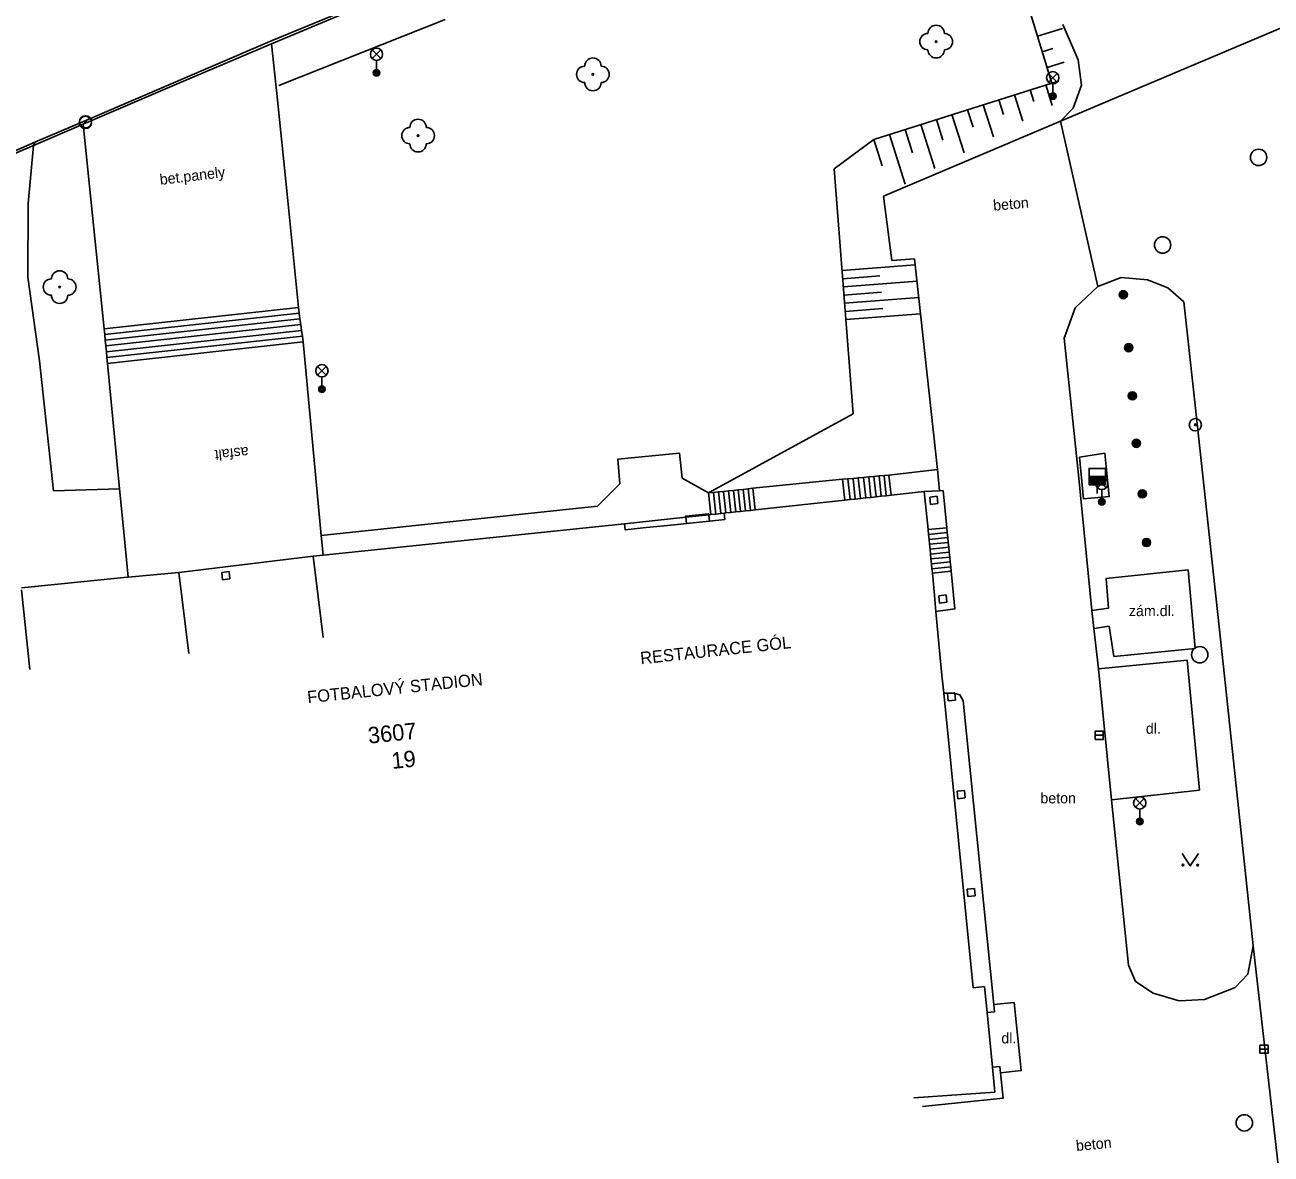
# Model space of a CAD drawing. Extents: x -539694 to -539148, y -1156467 to -1155920.
# Drawn here: x -539556.6 to -539480.5, y -1156122.8 to -1156053.8 of the extents above; entities that cross this region are included whole.
import ezdxf

# ---------------------------------------------------------------- set-up
doc = ezdxf.new("R2010")
doc.units = 0
for name, color, linetype in [('Vrstva 10', 7, 'Continuous'), ('Vrstva 11', 7, 'Continuous'), ('Vrstva 14', 7, 'Continuous'), ('Vrstva 15', 7, 'Continuous'), ('Vrstva 21', 7, 'Continuous'), ('Vrstva 22', 7, 'Continuous'), ('Vrstva 23', 7, 'Continuous'), ('Vrstva 25', 7, 'Continuous'), ('Vrstva 27', 7, 'Continuous'), ('Vrstva 28', 7, 'Continuous'), ('Vrstva 33', 7, 'Continuous'), ('Vrstva 36', 7, 'Continuous'), ('Vrstva 40', 7, 'Continuous'), ('Vrstva 41', 7, 'Continuous'), ('Vrstva 46', 7, 'Continuous'), ('Vrstva 47', 7, 'Continuous'), ('Vrstva 5', 7, 'Continuous'), ('Vrstva 6', 7, 'Continuous')]:
    doc.layers.add(name, color=color, linetype=linetype)

msp = doc.modelspace()

# ---------------------------------------------------------------- linework, layer by layer
at = {"layer": 'Vrstva 10'}
msp.add_lwpolyline([(-539514.829, -1156084.157), (-539514.87, -1156083.768), (-539514.877, -1156083.703), (-539516.27, -1156083.85), (-539516.263, -1156083.915), (-539516.222, -1156084.304)], dxfattribs=at)
at = {"layer": 'Vrstva 11'}
for p, q in [((-539493.4, -1156059.73), (-539469, -1156049.41)), ((-539541.52, -1156054.81), (-539532.19, -1156050.92)), ((-539541.55, -1156055), (-539532.14, -1156051.05)), ((-539553.04, -1156059.75), (-539541.52, -1156054.81)), ((-539547.07, -1156057.35), (-539541.55, -1156055)), ((-539541.55, -1156055), (-539541.23, -1156058.03)), ((-539553.06, -1156059.92), (-539547.07, -1156057.35)), ((-539541.23, -1156058.03), (-539540.61, -1156064.18)), ((-539556.09, -1156061.22), (-539553.06, -1156059.92)), ((-539556, -1156061.02), (-539553.04, -1156059.75)), ((-539552.48, -1156065.49), (-539553.06, -1156059.92)), ((-539493.4, -1156059.73), (-539504.2, -1156064.3)), ((-539493.4, -1156059.73), (-539491.13, -1156069.82)), ((-539556, -1156061.02), (-539562.35, -1156063.74)), ((-539562.25, -1156063.84), (-539556.09, -1156061.22)), ((-539556.09, -1156061.22), (-539556, -1156061.02)), ((-539540.61, -1156064.18), (-539539.916, -1156071.114)), ((-539551.767, -1156072.403), (-539552.48, -1156065.49)), ((-539502.31, -1156068.14), (-539500.9, -1156081)), ((-539555.72, -1156074.36), (-539556.44, -1156069.26)), ((-539485.14, -1156077.43), (-539485.88, -1156070.76)), ((-539551.767, -1156072.403), (-539539.916, -1156071.114)), ((-539551.735, -1156072.751), (-539539.868, -1156071.46)), ((-539551.703, -1156073.099), (-539539.819, -1156071.807)), ((-539551.671, -1156073.448), (-539539.771, -1156072.154)), ((-539551.639, -1156073.806), (-539539.721, -1156072.509)), ((-539551.606, -1156074.164), (-539539.672, -1156072.866)), ((-539493.17, -1156072.98), (-539492.31, -1156081.32)), ((-539539.625, -1156073.2), (-539551.573, -1156074.524)), ((-539538.523, -1156085.033), (-539539.625, -1156073.2)), ((-539554.86, -1156082.31), (-539555.72, -1156074.36)), ((-539483.4, -1156093.63), (-539485.14, -1156077.43)), ((-539505.106, -1156081.454), (-539504.972, -1156082.702)), ((-539504.788, -1156081.424), (-539504.654, -1156082.668)), ((-539504.478, -1156081.396), (-539504.345, -1156082.634)), ((-539504.17, -1156081.368), (-539504.037, -1156082.601)), ((-539503.87, -1156081.34), (-539503.737, -1156082.57)), ((-539500.9, -1156081), (-539500.79, -1156082.3)), ((-539492.31, -1156081.32), (-539491.48, -1156089.61)), ((-539550.828, -1156082.186), (-539554.86, -1156082.31)), ((-539516.5, -1156081.52), (-539514.88, -1156082.43)), ((-539512.766, -1156082.214), (-539512.624, -1156083.527)), ((-539512.468, -1156082.182), (-539512.326, -1156083.495)), ((-539512.17, -1156082.15), (-539506.7, -1156081.6)), ((-539512.17, -1156082.15), (-539512.028, -1156083.463)), ((-539506.7, -1156081.6), (-539506.563, -1156082.874)), ((-539506.38, -1156081.571), (-539506.244, -1156082.839)), ((-539506.062, -1156081.541), (-539505.926, -1156082.805)), ((-539505.743, -1156081.512), (-539505.608, -1156082.771)), ((-539505.425, -1156081.483), (-539505.29, -1156082.737)), ((-539514.88, -1156082.43), (-539514.74, -1156083.754)), ((-539514.576, -1156082.399), (-539514.433, -1156083.722)), ((-539514.268, -1156082.367), (-539514.125, -1156083.689)), ((-539513.96, -1156082.335), (-539513.817, -1156083.656)), ((-539513.662, -1156082.304), (-539513.519, -1156083.624)), ((-539513.364, -1156082.273), (-539513.221, -1156083.592)), ((-539513.064, -1156082.242), (-539512.922, -1156083.56)), ((-539501.72, -1156082.352), (-539500.79, -1156082.3)), ((-539538.523, -1156085.033), (-539521.66, -1156083.23)), ((-539550.614, -1156084.39), (-539550.303, -1156087.57)), ((-539538.412, -1156086.227), (-539538.523, -1156085.033)), ((-539500.341, -1156084.555), (-539501.486, -1156084.67)), ((-539500.311, -1156084.852), (-539501.455, -1156084.968)), ((-539500.281, -1156085.151), (-539501.425, -1156085.266)), ((-539500.251, -1156085.45), (-539501.395, -1156085.565)), ((-539500.22, -1156085.748), (-539501.365, -1156085.863)), ((-539500.19, -1156086.047), (-539501.335, -1156086.162)), ((-539500.16, -1156086.344), (-539501.305, -1156086.46)), ((-539500.13, -1156086.644), (-539501.275, -1156086.759)), ((-539500.1, -1156086.942), (-539501.245, -1156087.057)), ((-539500.072, -1156087.215), (-539501.218, -1156087.33)), ((-539490.61, -1156087.65), (-539485.6, -1156087.13)), ((-539491.48, -1156089.61), (-539491.36, -1156090.71)), ((-539491.36, -1156090.71), (-539491.08, -1156093.17)), ((-539491.08, -1156093.17), (-539485.66, -1156092.65)), ((-539485.66, -1156092.65), (-539484.91, -1156100.58)), ((-539491.08, -1156093.17), (-539490.28, -1156101.18)), ((-539481.64, -1156110.08), (-539483.4, -1156093.63)), ((-539499.34, -1156095.12), (-539497.47, -1156113.68)), ((-539484.91, -1156100.58), (-539490.28, -1156101.18)), ((-539490.28, -1156101.18), (-539489.24, -1156111.26)), ((-539481.97, -1156111.82), (-539481.64, -1156110.08)), ((-539481.64, -1156110.08), (-539479.7, -1156127.1))]:
    msp.add_line(p, q, dxfattribs=at)
for points in [[(-539493.4, -1156059.73), (-539492.62, -1156058.93), (-539492.11, -1156057.52), (-539492.33, -1156055.98), (-539493.25, -1156053.83)], [(-539556.44, -1156069.26), (-539556.41, -1156064.75), (-539556.09, -1156061.22)], [(-539504.2, -1156064.3), (-539503.69, -1156068.23), (-539502.31, -1156068.14)], [(-539485.88, -1156070.76), (-539486.85, -1156069.91), (-539488.09, -1156069.41), (-539489.69, -1156069.27), (-539491.13, -1156069.82)], [(-539491.13, -1156069.82), (-539492.51, -1156071.12), (-539493.17, -1156072.98)], [(-539539.916, -1156071.114), (-539539.868, -1156071.46), (-539539.819, -1156071.807), (-539539.771, -1156072.154), (-539539.721, -1156072.509), (-539539.672, -1156072.866), (-539539.625, -1156073.2)], [(-539551.573, -1156074.524), (-539551.606, -1156074.164), (-539551.639, -1156073.806), (-539551.671, -1156073.448), (-539551.703, -1156073.099), (-539551.735, -1156072.751), (-539551.767, -1156072.403)], [(-539551.573, -1156074.524), (-539550.828, -1156082.186), (-539550.614, -1156084.39)], [(-539521.66, -1156083.23), (-539520.29, -1156081.87), (-539520.42, -1156080.37), (-539516.66, -1156080), (-539516.5, -1156081.52)], [(-539492.25, -1156080.24), (-539490.7, -1156080), (-539490.42, -1156082.65), (-539491.99, -1156082.8), (-539492.25, -1156080.24)], [(-539506.7, -1156081.6), (-539506.38, -1156081.571), (-539506.062, -1156081.541), (-539505.743, -1156081.512), (-539505.425, -1156081.483), (-539505.106, -1156081.454), (-539504.788, -1156081.424), (-539504.478, -1156081.396), (-539504.17, -1156081.368), (-539503.87, -1156081.34), (-539500.9, -1156081)], [(-539514.88, -1156082.43), (-539514.576, -1156082.399), (-539514.268, -1156082.367), (-539513.96, -1156082.335), (-539513.662, -1156082.304), (-539513.364, -1156082.273), (-539513.064, -1156082.242), (-539512.766, -1156082.214), (-539512.468, -1156082.182), (-539512.17, -1156082.15)], [(-539500.79, -1156082.3), (-539500.57, -1156082.29), (-539500.341, -1156084.555), (-539500.311, -1156084.852), (-539500.281, -1156085.151), (-539500.251, -1156085.45), (-539500.22, -1156085.748), (-539500.19, -1156086.047), (-539500.16, -1156086.344), (-539500.13, -1156086.644), (-539500.1, -1156086.942), (-539500.072, -1156087.215), (-539499.84, -1156089.51), (-539501.007, -1156089.677)], [(-539485.6, -1156087.13), (-539485.18, -1156091.93), (-539490.15, -1156092.42)], [(-539491.48, -1156089.61), (-539490.46, -1156089.46), (-539490.61, -1156087.65)], [(-539490.15, -1156092.42), (-539490.43, -1156090.57), (-539491.36, -1156090.71)], [(-539500.53, -1156094.66), (-539500.118, -1156094.66), (-539499.93, -1156094.66), (-539499.85, -1156094.68), (-539499.54, -1156094.76), (-539499.34, -1156095.12)], [(-539489.24, -1156111.26), (-539488.82, -1156112.26), (-539487.75, -1156112.97), (-539486.15, -1156113.44), (-539484.61, -1156113.36), (-539482.74, -1156112.63), (-539481.97, -1156111.82)], [(-539497.47, -1156113.68), (-539497.43, -1156114.12), (-539497.88, -1156114.16)], [(-539497.47, -1156113.68), (-539496.23, -1156113.55), (-539495.8, -1156117.71), (-539497.06, -1156117.84)], [(-539497.06, -1156117.84), (-539496.9, -1156119.4), (-539501.826, -1156119.896)], [(-539497.06, -1156117.84), (-539497.1, -1156117.46), (-539497.55, -1156117.5)]]:
    msp.add_lwpolyline(points, dxfattribs=at)
at = {"layer": 'Vrstva 14'}
for p, q in [((-539493.93, -1156057.4), (-539495.35, -1156052.75)), ((-539504.79, -1156060.84), (-539493.93, -1156057.4)), ((-539504.79, -1156060.84), (-539507.219, -1156062.649)), ((-539506.049, -1156077.595), (-539507.219, -1156062.649)), ((-539514.88, -1156082.43), (-539506.049, -1156077.595))]:
    msp.add_line(p, q, dxfattribs=at)
at = {"layer": 'Vrstva 15'}
for p, q in [((-539494.806, -1156054.531), (-539493.276, -1156054.064)), ((-539494.514, -1156055.487), (-539493.871, -1156055.291)), ((-539494.222, -1156056.444), (-539493.178, -1156056.125)), ((-539495.257, -1156057.82), (-539495.031, -1156058.533)), ((-539494.304, -1156057.518), (-539493.909, -1156058.763)), ((-539493.93, -1156057.4), (-539493.529, -1156057.278)), ((-539497.163, -1156058.424), (-539496.881, -1156059.317)), ((-539496.21, -1156058.122), (-539495.702, -1156059.727)), ((-539500.023, -1156059.33), (-539499.287, -1156061.656)), ((-539499.07, -1156059.028), (-539498.73, -1156060.101)), ((-539498.117, -1156058.726), (-539497.494, -1156060.692)), ((-539501.93, -1156059.934), (-539501.079, -1156062.621)), ((-539500.977, -1156059.632), (-539500.58, -1156060.885)), ((-539504.79, -1156060.84), (-539504.279, -1156062.454)), ((-539503.837, -1156060.538), (-539502.871, -1156063.585)), ((-539502.883, -1156060.236), (-539502.429, -1156061.669)), ((-539502.266, -1156068.502), (-539506.733, -1156068.851)), ((-539504.43, -1156069.172), (-539506.693, -1156069.349)), ((-539502.157, -1156069.495), (-539506.654, -1156069.847)), ((-539504.334, -1156070.167), (-539506.615, -1156070.346)), ((-539502.049, -1156070.49), (-539506.576, -1156070.844)), ((-539504.238, -1156071.163), (-539506.537, -1156071.343)), ((-539501.94, -1156071.484), (-539506.498, -1156071.841))]:
    msp.add_line(p, q, dxfattribs=at)
at = {"layer": 'Vrstva 21'}
for centre, radius in [((-539552.91, -1156059.77), 0.375), ((-539552.92, -1156059.8), 0.375), ((-539552.92, -1156059.8), 0.05), ((-539552.91, -1156059.77), 0.05), ((-539485.17, -1156078.27), 0.375), ((-539485.17, -1156078.27), 0.05)]:
    msp.add_circle(centre, radius, dxfattribs=at)
at = {"layer": 'Vrstva 22'}
for centre in [(-539500.99, -1156054.87), (-539521.94, -1156056.87), (-539532.61, -1156060.61), (-539554.49, -1156069.86)]:
    msp.add_circle(centre, 0.05, dxfattribs=at)
for centre, start, end in [((-539500.99, -1156054.37), 0, 180), ((-539501.49, -1156054.87), 90, 270), ((-539500.49, -1156054.87), 270, 90), ((-539500.99, -1156055.37), 180, 0), ((-539521.94, -1156056.37), 0, 180), ((-539522.44, -1156056.87), 90, 270), ((-539521.44, -1156056.87), 270, 90), ((-539521.94, -1156057.37), 180, 0), ((-539533.11, -1156060.61), 90, 270), ((-539532.61, -1156060.11), 0, 180), ((-539532.11, -1156060.61), 270, 90), ((-539532.61, -1156061.11), 180, 0), ((-539554.49, -1156069.36), 0, 180), ((-539554.99, -1156069.86), 90, 270), ((-539553.99, -1156069.86), 270, 90), ((-539554.49, -1156070.36), 180, 0)]:
    msp.add_arc(centre, 0.5, start, end, dxfattribs=at)
at = {"layer": 'Vrstva 23'}
msp.add_line((-539541.12, -1156057.56), (-539530.96, -1156053.51), dxfattribs=at)
at = {"layer": 'Vrstva 25'}
for centre, radius in [((-539489.56, -1156070.32), 0.25), ((-539489.56, -1156070.32), 0.2), ((-539489.56, -1156070.32), 0.15), ((-539489.56, -1156070.32), 0.1), ((-539489.56, -1156070.32), 0.05), ((-539489.24, -1156073.56), 0.25), ((-539489.24, -1156073.56), 0.2), ((-539489.24, -1156073.56), 0.15), ((-539489.24, -1156073.56), 0.1), ((-539489.24, -1156073.56), 0.05), ((-539489.01, -1156076.5), 0.25), ((-539489.01, -1156076.5), 0.2), ((-539489.01, -1156076.5), 0.15), ((-539489.01, -1156076.5), 0.1), ((-539489.01, -1156076.5), 0.05), ((-539488.77, -1156079.4), 0.25), ((-539488.77, -1156079.4), 0.2), ((-539488.77, -1156079.4), 0.15), ((-539488.77, -1156079.4), 0.1), ((-539488.77, -1156079.4), 0.05), ((-539488.41, -1156082.49), 0.25), ((-539488.41, -1156082.49), 0.2), ((-539488.41, -1156082.49), 0.15), ((-539488.41, -1156082.49), 0.1), ((-539488.41, -1156082.49), 0.05), ((-539488.15, -1156085.46), 0.25), ((-539488.15, -1156085.46), 0.2), ((-539488.15, -1156085.46), 0.15), ((-539488.15, -1156085.46), 0.1), ((-539488.15, -1156085.46), 0.05)]:
    msp.add_circle(centre, radius, dxfattribs=at)
at = {"layer": 'Vrstva 27'}
for p, q in [((-539491.29, -1156097.23), (-539490.79, -1156097.23)), ((-539481.23, -1156116.4), (-539480.73, -1156116.4))]:
    msp.add_line(p, q, dxfattribs=at)
for points in [[(-539491.29, -1156097.48), (-539490.79, -1156097.48), (-539490.79, -1156096.98), (-539491.29, -1156096.98)], [(-539481.23, -1156116.65), (-539480.73, -1156116.65), (-539480.73, -1156116.15), (-539481.23, -1156116.15)]]:
    msp.add_lwpolyline(points, close=True, dxfattribs=at)
for centre in [(-539481.31, -1156061.94), (-539487.17, -1156067.29), (-539484.9, -1156092.31), (-539482.18, -1156120.9)]:
    msp.add_circle(centre, 0.5, dxfattribs=at)
at = {"layer": 'Vrstva 28'}
for p, q in [((-539491.66, -1156081.43), (-539490.66, -1156081.43)), ((-539491.66, -1156081.481), (-539490.66, -1156081.481)), ((-539491.66, -1156081.531), (-539490.66, -1156081.531)), ((-539491.66, -1156081.58), (-539490.66, -1156081.58)), ((-539491.66, -1156081.631), (-539490.66, -1156081.631)), ((-539491.66, -1156081.68), (-539490.66, -1156081.68)), ((-539491.66, -1156081.731), (-539490.66, -1156081.731)), ((-539491.66, -1156081.781), (-539490.66, -1156081.781)), ((-539491.66, -1156081.83), (-539490.66, -1156081.83)), ((-539491.66, -1156081.881), (-539490.66, -1156081.881)), ((-539491.16, -1156081.93), (-539491.16, -1156082.46))]:
    msp.add_line(p, q, dxfattribs=at)
msp.add_lwpolyline([(-539491.66, -1156081.93), (-539490.66, -1156081.93), (-539490.66, -1156080.93), (-539491.66, -1156080.93)], close=True, dxfattribs=at)
at = {"layer": 'Vrstva 33'}
for p, q in [((-539535.414, -1156055.911), (-539534.886, -1156055.381)), ((-539535.414, -1156055.381), (-539534.886, -1156055.911)), ((-539535.15, -1156056.02), (-539535.15, -1156056.77)), ((-539494.139, -1156057.339), (-539493.609, -1156056.809)), ((-539494.139, -1156056.809), (-539493.609, -1156057.339)), ((-539493.874, -1156057.449), (-539493.874, -1156058.199)), ((-539538.743, -1156075.235), (-539538.213, -1156074.705)), ((-539538.743, -1156074.705), (-539538.213, -1156075.235)), ((-539538.478, -1156075.345), (-539538.478, -1156076.095)), ((-539491.144, -1156082.111), (-539490.616, -1156081.581)), ((-539491.144, -1156081.581), (-539490.616, -1156082.111)), ((-539490.88, -1156082.22), (-539490.88, -1156082.97)), ((-539488.824, -1156101.631), (-539488.296, -1156101.101)), ((-539488.824, -1156101.101), (-539488.296, -1156101.631)), ((-539488.56, -1156101.74), (-539488.56, -1156102.49))]:
    msp.add_line(p, q, dxfattribs=at)
for centre, radius in [((-539535.15, -1156055.646), 0.375), ((-539535.15, -1156056.771), 0.2), ((-539535.15, -1156056.771), 0.145), ((-539535.15, -1156056.771), 0.0876), ((-539493.874, -1156057.074), 0.375), ((-539493.874, -1156058.199), 0.2), ((-539493.874, -1156058.199), 0.145), ((-539493.874, -1156058.199), 0.0876), ((-539538.478, -1156074.97), 0.375), ((-539538.478, -1156076.095), 0.2), ((-539538.478, -1156076.095), 0.145), ((-539538.478, -1156076.095), 0.0876), ((-539490.88, -1156081.846), 0.375), ((-539490.88, -1156082.971), 0.2), ((-539490.88, -1156082.971), 0.145), ((-539490.88, -1156082.971), 0.0876), ((-539488.56, -1156101.366), 0.375), ((-539488.56, -1156102.491), 0.2), ((-539488.56, -1156102.491), 0.145), ((-539488.56, -1156102.491), 0.0876)]:
    msp.add_circle(centre, radius, dxfattribs=at)
at = {"layer": 'Vrstva 36'}
msp.add_lwpolyline([(-539485.98, -1156104.46), (-539485.48, -1156105.21), (-539484.98, -1156104.46)], dxfattribs=at)
for centre in [(-539485.93, -1156105.16), (-539485.031, -1156105.16)]:
    msp.add_circle(centre, 0.05, dxfattribs=at)
at = {"layer": 'Vrstva 5'}
for p, q in [((-539506.563, -1156082.874), (-539512.028, -1156083.463)), ((-539506.244, -1156082.839), (-539506.563, -1156082.874)), ((-539505.926, -1156082.805), (-539506.244, -1156082.839)), ((-539505.608, -1156082.771), (-539505.926, -1156082.805)), ((-539505.29, -1156082.737), (-539505.608, -1156082.771)), ((-539504.972, -1156082.702), (-539505.29, -1156082.737)), ((-539504.654, -1156082.668), (-539504.972, -1156082.702)), ((-539504.345, -1156082.634), (-539504.654, -1156082.668)), ((-539504.037, -1156082.601), (-539504.345, -1156082.634)), ((-539503.737, -1156082.57), (-539504.037, -1156082.601)), ((-539501.72, -1156082.352), (-539503.737, -1156082.57)), ((-539501.486, -1156084.67), (-539501.72, -1156082.352)), ((-539501.383, -1156082.682), (-539500.935, -1156082.636)), ((-539501.337, -1156083.13), (-539501.383, -1156082.682)), ((-539500.935, -1156082.636), (-539500.889, -1156083.084)), ((-539514.433, -1156083.722), (-539514.74, -1156083.754)), ((-539514.125, -1156083.689), (-539514.433, -1156083.722)), ((-539513.926, -1156083.668), (-539514.125, -1156083.689)), ((-539513.817, -1156083.656), (-539513.926, -1156083.668)), ((-539513.926, -1156083.668), (-539513.885, -1156084.058)), ((-539513.519, -1156083.624), (-539513.817, -1156083.656)), ((-539513.221, -1156083.592), (-539513.519, -1156083.624)), ((-539512.922, -1156083.56), (-539513.221, -1156083.592)), ((-539512.624, -1156083.527), (-539512.922, -1156083.56)), ((-539512.326, -1156083.495), (-539512.624, -1156083.527)), ((-539512.028, -1156083.463), (-539512.326, -1156083.495)), ((-539500.889, -1156083.084), (-539501.337, -1156083.13)), ((-539520.004, -1156084.31), (-539538.412, -1156086.227)), ((-539516.263, -1156083.915), (-539520.004, -1156084.31)), ((-539520.004, -1156084.31), (-539519.965, -1156084.685)), ((-539516.967, -1156084.383), (-539518.687, -1156084.552)), ((-539516.967, -1156084.383), (-539516.222, -1156084.304)), ((-539514.87, -1156083.768), (-539516.263, -1156083.915)), ((-539516.222, -1156084.304), (-539514.829, -1156084.157)), ((-539514.74, -1156083.754), (-539514.87, -1156083.768)), ((-539514.829, -1156084.157), (-539513.885, -1156084.058)), ((-539518.687, -1156084.552), (-539519.965, -1156084.685)), ((-539501.455, -1156084.968), (-539501.486, -1156084.67)), ((-539501.425, -1156085.266), (-539501.455, -1156084.968)), ((-539501.395, -1156085.565), (-539501.425, -1156085.266)), ((-539501.365, -1156085.863), (-539501.395, -1156085.565)), ((-539501.335, -1156086.162), (-539501.365, -1156085.863)), ((-539539.009, -1156086.29), (-539547.213, -1156087.281)), ((-539538.412, -1156086.227), (-539539.009, -1156086.29)), ((-539539.009, -1156086.29), (-539538.409, -1156091.254)), ((-539501.305, -1156086.46), (-539501.335, -1156086.162)), ((-539501.275, -1156086.759), (-539501.305, -1156086.46)), ((-539501.245, -1156087.057), (-539501.275, -1156086.759)), ((-539547.213, -1156087.281), (-539550.303, -1156087.57)), ((-539547.213, -1156087.281), (-539546.613, -1156092.245)), ((-539544.593, -1156087.291), (-539544.146, -1156087.237)), ((-539544.539, -1156087.738), (-539544.593, -1156087.291)), ((-539544.146, -1156087.237), (-539544.092, -1156087.684)), ((-539501.22, -1156087.311), (-539501.245, -1156087.057)), ((-539501.218, -1156087.33), (-539501.22, -1156087.311)), ((-539501.103, -1156088.444), (-539501.218, -1156087.33)), ((-539550.562, -1156087.594), (-539556.826, -1156088.224)), ((-539550.303, -1156087.57), (-539550.562, -1156087.594)), ((-539544.092, -1156087.684), (-539544.539, -1156087.738)), ((-539556.813, -1156088.348), (-539556.312, -1156093.208)), ((-539501.103, -1156088.444), (-539501.007, -1156089.677)), ((-539500.831, -1156088.71), (-539500.383, -1156088.664)), ((-539500.785, -1156089.158), (-539500.831, -1156088.71)), ((-539500.383, -1156088.664), (-539500.337, -1156089.112)), ((-539501.007, -1156089.677), (-539500.99, -1156089.9)), ((-539500.337, -1156089.112), (-539500.785, -1156089.158)), ((-539500.99, -1156089.9), (-539500.7, -1156092.93)), ((-539500.7, -1156092.93), (-539500.64, -1156093.55)), ((-539500.64, -1156093.55), (-539500.53, -1156094.66)), ((-539500.53, -1156094.66), (-539498.74, -1156112.65)), ((-539500.303, -1156094.679), (-539500.118, -1156094.66)), ((-539500.257, -1156095.127), (-539500.303, -1156094.679)), ((-539499.809, -1156095.081), (-539500.257, -1156095.127)), ((-539500.118, -1156094.66), (-539499.855, -1156094.633)), ((-539499.855, -1156094.633), (-539499.85, -1156094.68)), ((-539499.85, -1156094.68), (-539499.809, -1156095.081)), ((-539499.71, -1156100.654), (-539499.262, -1156100.608)), ((-539499.664, -1156101.102), (-539499.71, -1156100.654)), ((-539499.216, -1156101.056), (-539499.664, -1156101.102)), ((-539499.262, -1156100.608), (-539499.216, -1156101.056)), ((-539499.101, -1156106.634), (-539498.653, -1156106.588)), ((-539499.055, -1156107.082), (-539499.101, -1156106.634)), ((-539498.607, -1156107.036), (-539499.055, -1156107.082)), ((-539498.653, -1156106.588), (-539498.607, -1156107.036)), ((-539498.74, -1156112.65), (-539498.04, -1156112.58)), ((-539498.04, -1156112.58), (-539497.88, -1156114.16)), ((-539497.88, -1156114.16), (-539497.55, -1156117.5)), ((-539497.55, -1156117.5), (-539497.4, -1156119.03)), ((-539497.4, -1156119.03), (-539502.359, -1156119.368))]:
    msp.add_line(p, q, dxfattribs=at)
at = {"layer": 'Vrstva 6'}
for p, q in [((-539516.967, -1156084.383), (-539518.687, -1156084.552)), ((-539501.103, -1156088.444), (-539501.218, -1156087.33)), ((-539500.7, -1156092.93), (-539500.99, -1156089.9)), ((-539500.53, -1156094.66), (-539500.64, -1156093.55)), ((-539497.55, -1156117.5), (-539497.88, -1156114.16))]:
    msp.add_line(p, q, dxfattribs=at)

# ---------------------------------------------------------------- texts
at = {"layer": 'Vrstva 40'}
for s, rotation, p in [('bet.panely', 6.84279, (-539548.34, -1156063.62)), ('beton', 5.14996, (-539497.481, -1156065.202)), ('asfalt', 185.66219, (-539542.986, -1156079.611)), ('beton', 5.73054, (-539492.422, -1156122.625))]:
    msp.add_text(s, height=0.65, rotation=rotation, dxfattribs=at).set_placement(p)
for s, p in [('zám.dl.', (-539489.227, -1156089.955)), ('dl.', (-539488.19, -1156097.14)), ('beton', (-539494.63, -1156101.39)), ('dl.', (-539497.01, -1156116.05))]:
    msp.add_text(s, height=0.65, dxfattribs=at).set_placement(p)
at = {"layer": 'Vrstva 41'}
for s, rotation, p in [('RESTAURACE GÓL', 6.15362, (-539519.009, -1156092.899)), ('FOTBALOVÝ STADION', 5.94779, (-539539.335, -1156095.28))]:
    msp.add_text(s, height=0.75, rotation=rotation, dxfattribs=at).set_placement(p)
at = {"layer": 'Vrstva 46'}
msp.add_text('19', height=1, rotation=5.94779, dxfattribs=at).set_placement((-539534.186, -1156099.29))
at = {"layer": 'Vrstva 47'}
msp.add_text('3607', height=1, rotation=5.94779, dxfattribs=at).set_placement((-539535.621, -1156097.747))

doc.saveas('drawing.dxf')
